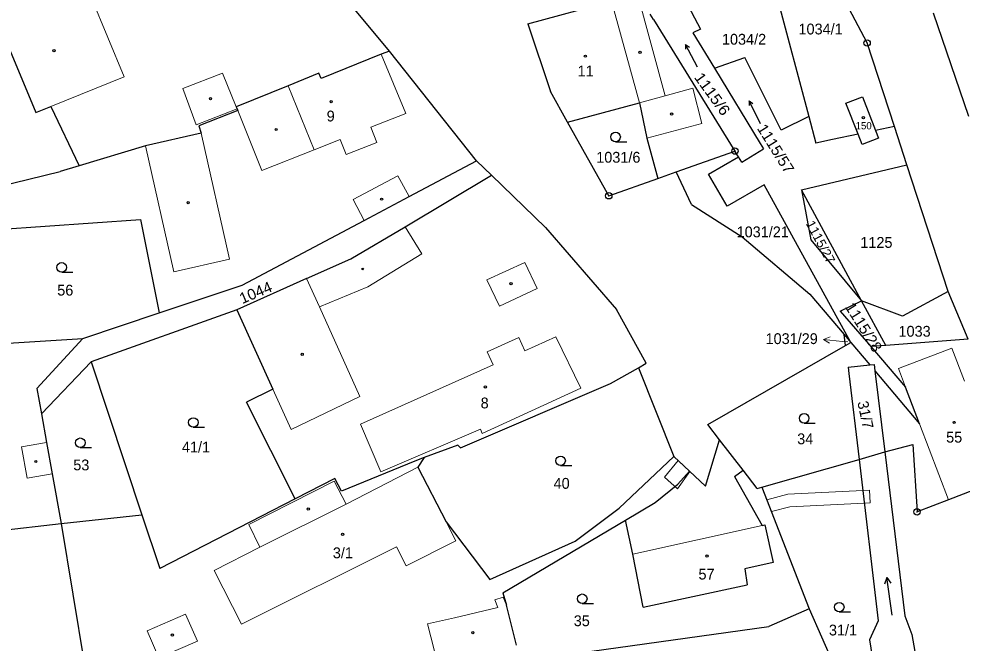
# Model space of a CAD drawing. Extents: x -618848 to -615803, y -1044450 to -1042254.
# Drawn here: x -617078.1 to -616929.8, y -1043244.1 to -1043145.8 of the extents above; entities that cross this region are included whole.
import ezdxf
from ezdxf.enums import TextEntityAlignment as Align

# ---------------------------------------------------------------- set-up
doc = ezdxf.new("R2010")
doc.units = 0
doc.header["$LTSCALE"] = 0.68
for name, color, linetype, lineweight in [('1', 7, 'Continuous', 25), ('13', 7, 'Continuous', 13), ('3', 7, 'Continuous', 25), ('4', 7, 'Continuous', 13), ('5', 7, 'Continuous', 25), ('7', 7, 'Continuous', 13), ('8', 7, 'Continuous', 25)]:
    doc.layers.add(name, color=color, linetype=linetype, lineweight=lineweight)
doc.layers.add('2', color=7, linetype='Continuous')

msp = doc.modelspace()

# ---------------------------------------------------------------- linework, layer by layer
at = {"layer": '1'}
for p, q in [((-616944.7, -1043149.64), (-616955.05, -1043129.79)), ((-617019.82, -1043150.93), (-617031.27, -1043137.1)), ((-616959.71, -1043139.31), (-616953.89, -1043161.2)), ((-616998.08, -1043146.64), (-616984.89, -1043143.08)), ((-616973.34, -1043142.9), (-616970.92, -1043147.45)), ((-616978.29, -1043145.95), (-616978.82, -1043145.1)), ((-616978.29, -1043145.95), (-616965.49, -1043166.65)), ((-616928.73, -1043161.2), (-616934.26, -1043144.93)), ((-617081.34, -1043146.45), (-617075.45, -1043160.59)), ((-616998.08, -1043146.64), (-616994.5, -1043157.29)), ((-616970.92, -1043147.45), (-616972.09, -1043148.07)), ((-616972.09, -1043148.07), (-616968.7, -1043153.63)), ((-616940.42, -1043162.79), (-616944.7, -1043149.64)), ((-617021.15, -1043151.41), (-617030.57, -1043155.25)), ((-617019.82, -1043150.93), (-617021.15, -1043151.41)), ((-617006.16, -1043168.16), (-617019.82, -1043150.93)), ((-616968.7, -1043153.63), (-616963.94, -1043151.94)), ((-616958.22, -1043163.37), (-616963.94, -1043151.94)), ((-617030.57, -1043155.25), (-617030.94, -1043154.41)), ((-616968.7, -1043153.63), (-616961.5, -1043165.45)), ((-616991.8, -1043162.12), (-616994.5, -1043157.29)), ((-616991.8, -1043162.12), (-616980.5, -1043159.06)), ((-616980.5, -1043159.06), (-616979.33, -1043164.64)), ((-616948.03, -1043159.09), (-616945.42, -1043158.1)), ((-616946.12, -1043163.99), (-616948.03, -1043159.09)), ((-616945.42, -1043158.1), (-616943.37, -1043163.41)), ((-617075.45, -1043160.59), (-617073.07, -1043159.63)), ((-617073.07, -1043159.63), (-617068.62, -1043168.96)), ((-617043.69, -1043160.28), (-617049.78, -1043162.69)), ((-617043.93, -1043159.68), (-617043.8, -1043160.01)), ((-617043.8, -1043160.01), (-617043.69, -1043160.28)), ((-616985.33, -1043173.69), (-616991.8, -1043162.12)), ((-616953.89, -1043161.2), (-616958.22, -1043163.37)), ((-616953.89, -1043161.2), (-616952.78, -1043165.4)), ((-617049.44, -1043163.85), (-617058.2, -1043165.82)), ((-617049.78, -1043162.69), (-617049.44, -1043163.85)), ((-616946.12, -1043163.99), (-616950.13, -1043164.84)), ((-616945.47, -1043165.64), (-616946.12, -1043163.99)), ((-616940.42, -1043162.79), (-616943.37, -1043163.41)), ((-616943.37, -1043163.41), (-616942.89, -1043164.64)), ((-616938.46, -1043168.82), (-616940.42, -1043162.79)), ((-616979.33, -1043164.64), (-616977.62, -1043170.96)), ((-616961.5, -1043165.45), (-616960.98, -1043166.3)), ((-616950.13, -1043164.84), (-616952.78, -1043165.4)), ((-616942.89, -1043164.64), (-616945.47, -1043165.64)), ((-617058.2, -1043165.82), (-617068.62, -1043168.96)), ((-616974.74, -1043169.94), (-616965.49, -1043166.65)), ((-616964.93, -1043167.56), (-616965.49, -1043166.65)), ((-616964.4, -1043168.41), (-616960.98, -1043166.3)), ((-617016.75, -1043173.79), (-617006.16, -1043168.16)), ((-617006.16, -1043168.16), (-617003.77, -1043170.46)), ((-616969.63, -1043170.27), (-616964.93, -1043167.56)), ((-616964.4, -1043168.41), (-616964.93, -1043167.56)), ((-617087.18, -1043173.67), (-617071.64, -1043169.87)), ((-617068.62, -1043168.96), (-617071.64, -1043169.87)), ((-616955.04, -1043172.75), (-616938.46, -1043168.82)), ((-616931.97, -1043188.74), (-616938.46, -1043168.82)), ((-617017.38, -1043178.56), (-617003.77, -1043170.46)), ((-617003.77, -1043170.46), (-616995.27, -1043178.65)), ((-616985.33, -1043173.69), (-616977.62, -1043170.96)), ((-616977.62, -1043170.96), (-616974.74, -1043169.94)), ((-616972.34, -1043175.08), (-616974.74, -1043169.94)), ((-616966.73, -1043175.31), (-616969.63, -1043170.27)), ((-616960.9, -1043171.95), (-616966.73, -1043175.31)), ((-616947.24, -1043196.75), (-616960.9, -1043171.95)), ((-616945.58, -1043190.2), (-616955.04, -1043172.75)), ((-616955.04, -1043172.75), (-616953.58, -1043180.63)), ((-617023.81, -1043177.55), (-617016.75, -1043173.79)), ((-616972.34, -1043175.08), (-616964.38, -1043180.16)), ((-617086.11, -1043179.28), (-617059, -1043177.42)), ((-617059, -1043177.42), (-617056.02, -1043192.11)), ((-617043, -1043187.77), (-617023.81, -1043177.55)), ((-617025.92, -1043183.63), (-617017.38, -1043178.56)), ((-616995.27, -1043178.65), (-616984.1, -1043191.6)), ((-616964.38, -1043180.16), (-616953.73, -1043189.16)), ((-616953.58, -1043180.63), (-616945.58, -1043190.2)), ((-617032.88, -1043186.68), (-617025.92, -1043183.63)), ((-617032.88, -1043186.68), (-617043.85, -1043191.61)), ((-617056.02, -1043192.11), (-617043, -1043187.77)), ((-616953.73, -1043189.16), (-616948.31, -1043195.5)), ((-616931.97, -1043188.74), (-616939.13, -1043192.63)), ((-616928.83, -1043196.23), (-616931.97, -1043188.74)), ((-616948.92, -1043191.83), (-616945.58, -1043190.2)), ((-616939.13, -1043192.63), (-616945.58, -1043190.2)), ((-616941.77, -1043197.23), (-616945.58, -1043190.2)), ((-617068.06, -1043196.12), (-617056.02, -1043192.11)), ((-617043.85, -1043191.61), (-617066.75, -1043199.8)), ((-617043.85, -1043191.61), (-617038.18, -1043204.1)), ((-616979.44, -1043200.01), (-616984.1, -1043191.6)), ((-616948.92, -1043191.83), (-616944.13, -1043197.41)), ((-617082.72, -1043197.03), (-617068.06, -1043196.12)), ((-617068.06, -1043196.12), (-617075.29, -1043203.99)), ((-616948.31, -1043195.5), (-616947.24, -1043196.75)), ((-616948.1, -1043197.24), (-616948.31, -1043195.5)), ((-616928.83, -1043196.23), (-616941.77, -1043197.23)), ((-616969.75, -1043209.66), (-616948.1, -1043197.24)), ((-616948.1, -1043197.24), (-616947.24, -1043196.75)), ((-616947.24, -1043196.75), (-616944.26, -1043200.29)), ((-616941.77, -1043197.23), (-616944.13, -1043197.41)), ((-616944.13, -1043197.41), (-616938.68, -1043203.79)), ((-617066.75, -1043199.8), (-617074.57, -1043207.99)), ((-617066.75, -1043199.8), (-617058.77, -1043223.86)), ((-616985.07, -1043203.24), (-616980.68, -1043200.75)), ((-616980.68, -1043200.75), (-616979.44, -1043200.01)), ((-616980.68, -1043200.75), (-616975.08, -1043214.71)), ((-616947.7, -1043200.65), (-616944.26, -1043200.29)), ((-616947.7, -1043200.65), (-616947.58, -1043201.64)), ((-616944.26, -1043200.29), (-616943.6, -1043200.23)), ((-616943.6, -1043200.23), (-616943.48, -1043201.22)), ((-616947.58, -1043201.64), (-616945.96, -1043215.19)), ((-616943.48, -1043201.22), (-616941.9, -1043213.99)), ((-616943.48, -1043201.22), (-616936.48, -1043209.55)), ((-617075.29, -1043203.99), (-617074.57, -1043207.99)), ((-617008.63, -1043213.34), (-616985.07, -1043203.24)), ((-616936.48, -1043209.55), (-616938.68, -1043203.79)), ((-617038.18, -1043204.1), (-617042.31, -1043206.17)), ((-617034.67, -1043221.35), (-617042.31, -1043206.17)), ((-617074.57, -1043207.99), (-617073.75, -1043212.5)), ((-616967.91, -1043212.06), (-616969.75, -1043209.66)), ((-617073.75, -1043212.5), (-617072.86, -1043217.42)), ((-617009.09, -1043212.93), (-617014.36, -1043214.87)), ((-617008.63, -1043213.34), (-617009.09, -1043212.93)), ((-616970.14, -1043219.37), (-616967.91, -1043212.06)), ((-616964.18, -1043216.87), (-616967.91, -1043212.06)), ((-616941.9, -1043213.99), (-616937.5, -1043212.81)), ((-616937.5, -1043212.81), (-616936.85, -1043223.42)), ((-616945.96, -1043215.19), (-616941.9, -1043213.99)), ((-616941.9, -1043213.99), (-616938.77, -1043239.78)), ((-617015.86, -1043215.42), (-617027.38, -1043220.14)), ((-617014.36, -1043214.87), (-617015.86, -1043215.42)), ((-617014.36, -1043214.87), (-617015.35, -1043216.36)), ((-616983.71, -1043222.86), (-616975.08, -1043214.71)), ((-616975.08, -1043214.71), (-616972.64, -1043216.99)), ((-616961.27, -1043219.51), (-616945.96, -1043215.19)), ((-616945.96, -1043215.19), (-616942.94, -1043240.58)), ((-617015.35, -1043216.36), (-617010.9, -1043225)), ((-616974.45, -1043219.08), (-616972.64, -1043216.99)), ((-616972.64, -1043216.99), (-616970.14, -1043219.37)), ((-616965.56, -1043217.85), (-616964.18, -1043216.87)), ((-616961.98, -1043219.72), (-616964.18, -1043216.87)), ((-617072.86, -1043217.42), (-617071.44, -1043225.27)), ((-617028.41, -1043218.18), (-617034.67, -1043221.35)), ((-617027.38, -1043220.14), (-617028.41, -1043218.18)), ((-616965.56, -1043217.85), (-616961.21, -1043225.56)), ((-616923.46, -1043218.28), (-616931.9, -1043221.52)), ((-616978.04, -1043221.92), (-616974.45, -1043219.08)), ((-616961.98, -1043219.72), (-616961.27, -1043219.51)), ((-616961.27, -1043219.51), (-616953.81, -1043238.68)), ((-617034.67, -1043221.35), (-617055.95, -1043232.35)), ((-616931.9, -1043221.52), (-616936.85, -1043223.42)), ((-616990.6, -1043228.04), (-616983.71, -1043222.86)), ((-616982.7, -1043224.74), (-616978.04, -1043221.92)), ((-617071.44, -1043225.27), (-617058.77, -1043223.86)), ((-617058.77, -1043223.86), (-617055.95, -1043232.35)), ((-617002.01, -1043236.17), (-616982.7, -1043224.74)), ((-616981.53, -1043230.06), (-616982.7, -1043224.74)), ((-617105.95, -1043229.1), (-617071.44, -1043225.27)), ((-617071.44, -1043225.27), (-617067.07, -1043251.7)), ((-617010.9, -1043225), (-617004.04, -1043234.05)), ((-616961.21, -1043225.56), (-616960.79, -1043225.47)), ((-616960.79, -1043225.47), (-616959.48, -1043231.41)), ((-617004.04, -1043234.05), (-616990.6, -1043228.04)), ((-616979.91, -1043238.42), (-616981.53, -1043230.06)), ((-616959.48, -1043231.41), (-616963.95, -1043232.4)), ((-616963.95, -1043232.4), (-616963.58, -1043234.88)), ((-616979.91, -1043238.42), (-616963.58, -1043234.88)), ((-617002.01, -1043236.17), (-617001.43, -1043238.1)), ((-616999.87, -1043244.41), (-617001.43, -1043238.1)), ((-616953.81, -1043238.68), (-616960.17, -1043241.44)), ((-616953.81, -1043238.68), (-616945.8, -1043256.94)), ((-616942.94, -1043240.58), (-616944.31, -1043243.57)), ((-616938.77, -1043239.78), (-616937.69, -1043242.72)), ((-616998.89, -1043246.85), (-616960.17, -1043241.44)), ((-616944.31, -1043243.57), (-616942.31, -1043256.16)), ((-616937.69, -1043242.72), (-616935.42, -1043255.02))]:
    msp.add_line(p, q, dxfattribs=at)
msp.add_lwpolyline([(-617030.94, -1043154.41), (-617035.78, -1043156.37), (-617043.93, -1043159.68)], dxfattribs=at)
at = {"layer": '13'}
for points in [[(-616974.52, -1043219.79), (-616972.6, -1043217.05), (-616974.4, -1043215.35), (-616976.57, -1043217.95)], [(-616956.87, -1043222.64), (-616945.14, -1043222.07), (-616944.22, -1043222.02), (-616944.32, -1043220.02), (-616945.38, -1043220.07), (-616957.17, -1043220.66), (-616960.49, -1043221.5), (-616959.76, -1043223.38)]]:
    msp.add_lwpolyline(points, close=True, dxfattribs=at)
at = {"layer": '3'}
for p, q in [((-616973.254, -1043149.892), (-616972.65, -1043150.313)), ((-616963.241, -1043158.741), (-616962.652, -1043159.182)), ((-616984.263, -1043165.18), (-616982.513, -1043165.18)), ((-617071.373, -1043185.7), (-617069.623, -1043185.7)), ((-616954.603, -1043209.45), (-616952.853, -1043209.45)), ((-617050.673, -1043210.1), (-617048.923, -1043210.1)), ((-617068.443, -1043213.29), (-617066.693, -1043213.29)), ((-616992.913, -1043216.13), (-616991.163, -1043216.13)), ((-616941.611, -1043233.741), (-616940.979, -1043234.639)), ((-616989.503, -1043237.84), (-616987.753, -1043237.84)), ((-616949.083, -1043239.16), (-616947.333, -1043239.16))]:
    msp.add_line(p, q, dxfattribs=at)
for points in [[(-616971.367, -1043153.442), (-616973.254, -1043149.892), (-616973.243, -1043150.628)], [(-616961.479, -1043162.354), (-616963.241, -1043158.741), (-616963.256, -1043159.476)], [(-616940.776, -1043239.683), (-616941.611, -1043233.741), (-616941.972, -1043234.778)]]:
    msp.add_lwpolyline(points, dxfattribs=at)
for centre in [(-616984.2629, -1043164.4298), (-617071.3729, -1043184.9498), (-616954.6029, -1043208.6998), (-617050.6729, -1043209.3498), (-617068.4429, -1043212.5398), (-616992.9129, -1043215.3798), (-616989.5029, -1043237.0898), (-616949.0829, -1043238.4098)]:
    msp.add_circle(centre, 0.75, dxfattribs=at)
at = {"layer": '4'}
for p, q in [((-617067.49, -1043140.68), (-617061.54, -1043154.96)), ((-616984.89, -1043143.08), (-616980.5, -1043159.06)), ((-617021.15, -1043151.41), (-617017.25, -1043160.72)), ((-617073.07, -1043159.63), (-617061.54, -1043154.96)), ((-617052.33, -1043156.79), (-617046.1, -1043154.38)), ((-617046.1, -1043154.38), (-617043.93, -1043159.68)), ((-617052.33, -1043156.79), (-617050.23, -1043162.54)), ((-616976.45, -1043157.94), (-616972.12, -1043156.73)), ((-616972.12, -1043156.73), (-616970.68, -1043162.31)), ((-617050.23, -1043162.54), (-617043.8, -1043160.01)), ((-617039.91, -1043169.73), (-617043.69, -1043160.28)), ((-617017.25, -1043160.72), (-617022.75, -1043162.91)), ((-616979.33, -1043164.64), (-616970.68, -1043162.31)), ((-617049.44, -1043163.85), (-617044.99, -1043183.66)), ((-617022.75, -1043162.91), (-617021.82, -1043165.32)), ((-617027.57, -1043164.82), (-617031.66, -1043166.45)), ((-617026.66, -1043167.18), (-617027.57, -1043164.82)), ((-617021.82, -1043165.32), (-617026.66, -1043167.18)), ((-617058.2, -1043165.82), (-617053.75, -1043185.63)), ((-617025.55, -1043174.29), (-617023.81, -1043177.55)), ((-617017.38, -1043178.56), (-617014.76, -1043182.82)), ((-617023.22, -1043188.02), (-617014.76, -1043182.82)), ((-617053.75, -1043185.63), (-617044.99, -1043183.66)), ((-617004.49, -1043186.92), (-616998.55, -1043184.18)), ((-616998.55, -1043184.18), (-616996.61, -1043188.28)), ((-617030.85, -1043191.17), (-617032.88, -1043186.68)), ((-617002.53, -1043191.05), (-617004.49, -1043186.92)), ((-617023.22, -1043188.02), (-617030.85, -1043191.17)), ((-616996.61, -1043188.28), (-617002.53, -1043191.05)), ((-617024.46, -1043205.29), (-617030.85, -1043191.17)), ((-617004.44, -1043198.25), (-616999.47, -1043195.99)), ((-616999.47, -1043195.99), (-616998.55, -1043198.07)), ((-616998.55, -1043198.07), (-616993.68, -1043195.89)), ((-616989.72, -1043203.97), (-616993.68, -1043195.89)), ((-616939.79, -1043200.88), (-616931.36, -1043197.66)), ((-616931.36, -1043197.66), (-616929.38, -1043202.83)), ((-617003.52, -1043200.29), (-617004.44, -1043198.25)), ((-617024.39, -1043209.63), (-617003.52, -1043200.29)), ((-616938.68, -1043203.79), (-616939.79, -1043200.88)), ((-617005.22, -1043211.11), (-616989.72, -1043203.97)), ((-617038.18, -1043204.1), (-617035.29, -1043210.46)), ((-617035.29, -1043210.46), (-617024.46, -1043205.29)), ((-617024.39, -1043209.63), (-617021.19, -1043217.12)), ((-616931.9, -1043221.52), (-616936.48, -1043209.55)), ((-617021.19, -1043217.12), (-617005.52, -1043210.42)), ((-617005.52, -1043210.42), (-617005.22, -1043211.11)), ((-617015.35, -1043216.36), (-617026.63, -1043222.23)), ((-617072.86, -1043217.42), (-617076.8, -1043218.13)), ((-617028.54, -1043218.58), (-617041.96, -1043225.39)), ((-617026.63, -1043222.23), (-617028.54, -1043218.58)), ((-617010.9, -1043225), (-617009.37, -1043227.96)), ((-616981.53, -1043230.06), (-616961.21, -1043225.56)), ((-617040.22, -1043228.99), (-617047.39, -1043232.62)), ((-617018.73, -1043228.91), (-617043.08, -1043241.07)), ((-617017.22, -1043231.89), (-617018.73, -1043228.91)), ((-617009.37, -1043227.96), (-617017.22, -1043231.89)), ((-617047.39, -1043232.62), (-617043.08, -1043241.07)), ((-617003.24, -1043237.28), (-617001.92, -1043236.85)), ((-617002.8, -1043238.48), (-617003.24, -1043237.28)), ((-617001.92, -1043236.85), (-617001.43, -1043238.1)), ((-617057.95, -1043242.12), (-617051.88, -1043239.49)), ((-617051.88, -1043239.49), (-617050, -1043243.74)), ((-617009.6, -1043240.09), (-617002.8, -1043238.48)), ((-617013.83, -1043241.04), (-617009.6, -1043240.09)), ((-617012.23, -1043247.36), (-617013.83, -1043241.04)), ((-617056.1, -1043246.37), (-617057.95, -1043242.12)), ((-617050, -1043243.74), (-617056.1, -1043246.37))]:
    msp.add_line(p, q, dxfattribs=at)
for points in [[(-616980.5, -1043159.06), (-616976.45, -1043157.94), (-616980.82, -1043141.93)], [(-617035.78, -1043156.37), (-617031.66, -1043166.45), (-617039.91, -1043169.73)], [(-617016.75, -1043173.79), (-617018.49, -1043170.53), (-617025.55, -1043174.29)], [(-617076.8, -1043218.13), (-617077.69, -1043213.21), (-617073.75, -1043212.5)], [(-617041.96, -1043225.39), (-617040.22, -1043228.99), (-617026.63, -1043222.23)]]:
    msp.add_lwpolyline(points, dxfattribs=at)
at = {"layer": '5'}
for centre, radius in [((-617072.5868, -1043150.8592), 0.175), ((-616989.0168, -1043151.7192), 0.175), ((-616980.4168, -1043151.1092), 0.175), ((-617047.9768, -1043158.3992), 0.175), ((-617028.9868, -1043158.8892), 0.175), ((-616975.4568, -1043160.8192), 0.175), ((-616945.2868, -1043161.3992), 0.175), ((-617037.6398, -1043163.2532), 0.175), ((-617021.0668, -1043174.2192), 0.175), ((-617051.4768, -1043174.7692), 0.175), ((-617024.0346, -1043185.1994), 0.1172), ((-617000.7068, -1043187.5292), 0.175), ((-617033.5468, -1043198.6392), 0.175), ((-617004.7368, -1043203.7592), 0.175), ((-616931.0168, -1043209.3492), 0.175), ((-617075.4468, -1043215.4992), 0.175), ((-617032.5968, -1043222.9692), 0.175), ((-617027.1868, -1043226.9492), 0.175), ((-616969.8768, -1043230.3792), 0.175), ((-617006.7068, -1043242.4192), 0.175), ((-617053.9668, -1043242.8092), 0.175)]:
    msp.add_circle(centre, radius, dxfattribs=at)
at = {"layer": '7'}
msp.add_line((-616951.565, -1043196.286), (-616950.621, -1043196.889), dxfattribs=at)
msp.add_lwpolyline([(-616947.76, -1043196.69), (-616948.58, -1043196.6), (-616951.565, -1043196.286), (-616950.516, -1043195.893)], dxfattribs=at)
at = {"layer": '8'}
for centre, radius in [((-616944.7, -1043149.6399), 0.5), ((-616944.7, -1043149.6399), 0.0303), ((-616965.49, -1043166.6499), 0.5), ((-616965.49, -1043166.6499), 0.0303), ((-616985.33, -1043173.6899), 0.5), ((-616985.33, -1043173.6899), 0.0303), ((-616936.85, -1043223.4199), 0.5), ((-616936.85, -1043223.4199), 0.0303)]:
    msp.add_circle(centre, radius, dxfattribs=at)

# ---------------------------------------------------------------- texts
at = {"layer": '2'}
for s, height, p in [('1034/1', 1.7, (-616952.02, -1043148.295)), ('1034/2', 1.7, (-616964.06, -1043149.905)), ('11', 1.7, (-616988.979, -1043154.895)), ('9', 1.7, (-617029.07, -1043161.985)), ('150', 1.139, (-616945.249, -1043163.234)), ('1031/6', 1.7, (-616983.83, -1043168.475)), ('1031/21', 1.7, (-616961.119, -1043180.215)), ('1125', 1.7, (-616943.24, -1043181.875)), ('56', 1.7, (-617070.809, -1043189.385)), ('1033', 1.7, (-616937.24, -1043195.855)), ('1031/29', 1.7, (-616956.569, -1043197.015)), ('8', 1.7, (-617004.85, -1043207.135)), ('34', 1.7, (-616954.439, -1043212.775)), ('55', 1.7, (-616931.009, -1043212.525)), ('41/1', 1.7, (-617050.259, -1043214.075)), ('53', 1.7, (-617068.289, -1043216.885)), ('40', 1.7, (-616992.749, -1043219.785)), ('3/1', 1.7, (-617027.15, -1043230.715)), ('57', 1.7, (-616969.959, -1043234.065)), ('35', 1.7, (-616989.579, -1043241.405)), ('31/1', 1.7, (-616948.499, -1043242.865))]:
    msp.add_text(s, height=height, dxfattribs=at).set_placement(p, align=Align.CENTER)
for s, height, rotation, width, p in [('1115/6', 1.7, 306, 1.1, (-616969.7386, -1043158.1539)), ('1115/57', 1.7, 302, 1.05, (-616959.7971, -1043166.7241)), ('1115/27', 1.443, 298, 1.05, (-616952.6568, -1043181.2918)), ('1044', 1.7, 23, 1.05, (-617040.5441, -1043189.6991)), ('1115/28', 1.7, 302, 1.05, (-616945.9671, -1043194.8141))]:
    msp.add_text(s, height=height, rotation=rotation, dxfattribs=dict(at, width=width)).set_placement(p, align=Align.CENTER)
msp.add_text('31/7', height=1.7, rotation=282, dxfattribs=at).set_placement((-616945.7862, -1043208.3278), align=Align.CENTER)

doc.saveas('drawing.dxf')
